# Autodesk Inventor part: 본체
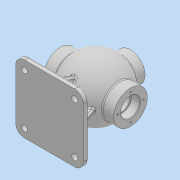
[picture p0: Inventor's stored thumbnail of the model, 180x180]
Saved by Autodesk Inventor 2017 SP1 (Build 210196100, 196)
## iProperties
Part Number: 본체
Material: 일반
Document SubType Name: Modeling
Designer: MRC
Density: 1 g/cm^3
Appearance: 기본값
Author: MRC
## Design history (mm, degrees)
sketch "스케치1"
  geometry: L1 (-65, 0)-(65, 0); L2 (-65, 0)-(-65, 31); L3 (-65, 31)-(-44.215, 31); L4 (65, 0)-(65, 31); L5 (65, 31)-(44.215, 31); L6 (-65, 17.5)-(-49, 17.5); L7 (-49, 17.5)-(-49, 15); L8 (-49, 15)-(-41.364, 15); L9 (65, 17.5)-(49, 17.5); L10 (49, 17.5)-(49, 15); L11 (49, 15)-(41.364, 15); A1 r 54 centre (0, 0) between (44.215, 31) and (-44.215, 31); A2 r 44 centre (0, 0) between (41.364, 15) and (-41.364, 15); 2 further points
  constraints: 22 end point, 5 perpendicular, 5 point on line, 4 point on circle, 3 coincident, 2 centre point, 2 horizontal, 2 vertical, 1 midpoint
  dimensions: "d0" = 130 distance of L1.start L1.end; "d1" = 108 diameter of A1; "d2" = 62 diameter of L5 L1; "d3" = 62 diameter of L3 L1; "d4" = 88 diameter of A2; "d5" = 35 diameter of L9 L1; "d6" = 16 distance of L9.start L9.end; "d7" = 16 distance of L6.start L6.end; "d8" = 30 diameter of L8 L1
revolve "회전1" sketch "스케치1" stored, may be unused: angle "d9" = 90 deg
chamfer "모따기1" distance "d10" = 1; stored, may be unused: second distance "d11" = 2, angle "d12" = 45 deg
chamfer "모따기2" distance "d13" = 1; stored, may be unused: second distance "d14" = 2, angle "d15" = 45 deg
fillet "모깎기1" dims "d16" = 0.6
node "작업 평면1"
sketch "스케치2"
  geometry: L1 (62.5, -62.5)-(-62.5, -62.5); L2 (-62.5, -62.5)-(-62.5, 62.5); L3 (-62.5, 62.5)-(62.5, 62.5); L4 (62.5, 62.5)-(62.5, -62.5); L5 (62.5, -62.5)-(-62.5, 62.5); L6 (-62.5, -62.5)-(62.5, 62.5); 1 further point
  constraints: 12 end point, 2 midpoint, 2 parallel, 2 perpendicular, 1 horizontal
  dimensions: "d18" = 125 distance of L2.end L3.end
sketch "스케치3"
  geometry: C1 r 31 at (0, 0) reference; 1 further point
  constraints: 1 vertical alignment
  dimensions: "d19" = 24 distance of point (0, 24) C1.centre
hole "구멍1" sketch "스케치3" at (0, 24) diameter "d20" = 3.242; stored, may be unused: countersink angle "d24" = 90 deg, drill point angle "d26" = 118 deg; dims "d21" = 12, "d22" = 4, "d23" = 2, "d25" = 15
node "작업 평면2"
sketch "스케치4"
  geometry: C1 r 27 at (0, 0); 1 further point
  constraints: 1 centre point, 1 coincident
  dimensions: "d31" = 54 diameter of C1
extrude "돌출1" join sketch "스케치4" stored distance "d32" = 10; taper "d33" = 0 deg
sketch "스케치5"
  geometry: C1 r 27 at (0, 0) reference; C2 r 13 at (0, 0)
  constraints: 1 centre point, 1 coincident
  dimensions: "d34" = 26 diameter of C2
extrude "돌출2" cut sketch "스케치5" stored distance "d35" = 0; taper "d36" = 0 deg
sketch "스케치6"
  geometry: C1 r 13 at (0, 0) reference; 1 further point
  constraints: 1 vertical alignment
  dimensions: "d37" = 20 distance of C1.centre point (0, 20)
hole "구멍2" sketch "스케치6" at (0, 20) diameter "d38" = 3.242; stored, may be unused: countersink angle "d42" = 90 deg, drill point angle "d44" = 118 deg; dims "d39" = 9, "d40" = 4, "d41" = 2, "d43" = 11
extrude "돌출3" join sketch "스케치2" distance "d48" = 10; taper "d49" = 0 deg
fillet "모깎기2" dims "d50" = 16
fillet "모깎기3" dims "d51" = 3
sketch "스케치7"
  geometry: L1 (-75, -50.5)-(-50.777, -41.684); L2 (-75, 50.5)-(-58.826, 44.613); L3 (-78, -62.5)-(-85, -62.5) reference; L4 (-75, 46.5)-(-75, -46.5) reference; L5 (-85, 62.5)-(-78, 62.5) reference; 1 further point
  constraints: 4 end point, 2 point on line
  dimensions: "d52" = 20 deg angle of L1 L3; "d53" = 12 distance from line of L1.start L3; "d54" = 20 deg angle of L2 L5; "d55" = 12 distance from line of L2.start L5
feature "리브1" dims "d56" = 30, "d57" = 8, "d58" = 0, "d59" = 0, "d60" = 1, "d61" = 1
feature "리브2" dims "d62" = 30, "d63" = 8, "d64" = 0, "d65" = 0, "d66" = 1, "d67" = 1
sketch "스케치8"
  geometry: L1 (50.5, -75)-(43.286, -55.179); L2 (-50.5, -75)-(-43.704, -56.329); L3 (62.5, -85)-(62.5, -78) reference; L4 (-62.5, -78)-(-62.5, -85) reference; L5 (46.5, -75)-(-46.5, -75) reference; 1 further point
  constraints: 4 end point, 2 point on line
  dimensions: "d68" = 12 distance from line of L1.start L3; "d69" = 20 deg angle of L3 L1; "d70" = 20 deg angle of L2 L4; "d71" = 12 distance from line of L4 L2.start
feature "리브3" dims "d72" = 30, "d73" = 8, "d74" = 0, "d75" = 0, "d76" = 1, "d77" = 1
feature "리브4" dims "d78" = 30, "d79" = 8, "d80" = 0, "d81" = 0, "d82" = 1, "d83" = 1
fillet "모깎기4" dims "d84" = 3
fillet "모깎기5" dims "d85" = 3
fillet "모깎기6" dims "d86" = 3
chamfer "모따기3" distance "d87" = 1; stored, may be unused: second distance "d88" = 2, angle "d89" = 45 deg
fillet "모깎기7" dims "d90" = 3
node "작업 평면3"
sketch "스케치9"
  geometry: L1 (-27, 65)-(27, 65) reference; 2 further points
  constraints: 1 vertical alignment, 1 other
  dimensions: "d92" = 9 distance from line of point (0, 56) L1
feature "엠보싱1" sketch "스케치9" dims "d0" = 130, "d93" = 0.5, "d94" = 0
sketch "스케치10"
  geometry: C1 r 5.5 at (-46.5, -46.5); C2 r 5.5 at (-46.5, 46.5); C3 r 5.5 at (46.5, 46.5); C4 r 5.5 at (46.5, -46.5); A1 r 13 centre (46.5, 46.5) between (59.5, 46.5) and (46.5, 59.5) reference; A2 r 13 centre (-46.5, 46.5) between (-46.5, 59.5) and (-59.5, 46.5) reference; A3 r 13 centre (-46.5, -46.5) between (-59.5, -46.5) and (-46.5, -59.5) reference; A4 r 13 centre (46.5, -46.5) between (46.5, -59.5) and (59.5, -46.5) reference; 1 further point
  constraints: 4 centre point, 4 coincident
  dimensions: "d95" = 11 diameter of C1; "d96" = 11 diameter of C2; "d97" = 11 diameter of C3; "d98" = 11 diameter of C4
extrude "돌출4" cut sketch "스케치10" stored distance "d99" = 10; taper "d100" = 0 deg
node "솔리드1"
pattern_circular "원형 패턴1" dims angle "d28" = 360 deg
mirror "미러1"
pattern_circular "원형 패턴2" dims angle "d46" = 360 deg
other parameters: "d17" = -85, "d30" = 65, "d91" = -59.75
